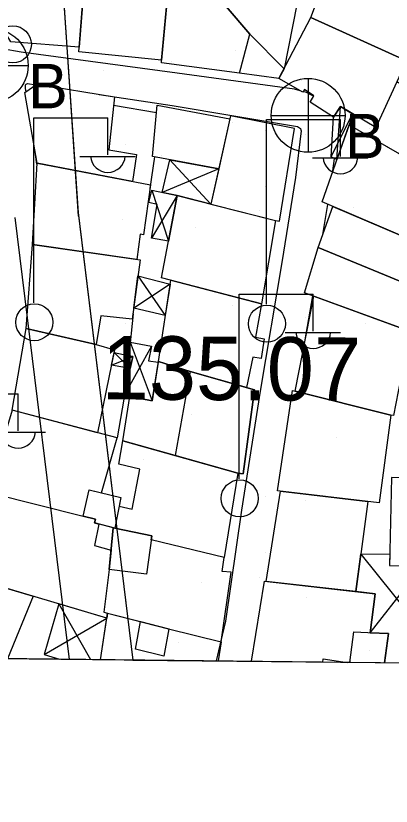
# Model space of a CAD drawing. Extents: x 417997 to 421451, y 4451742 to 4455216.
# Drawn here: x 419917.2 to 419952.7, y 4452223.3 to 4452298.1 of the extents above; entities that cross this region are included whole.
import ezdxf

# ---------------------------------------------------------------- set-up
doc = ezdxf.new("R2010")
doc.units = 0
for name, color, linetype in [('ADAKENARI', 7, 'Continuous'), ('B_Mesken', 7, 'Continuous'), ('B_Sundurma', 7, 'Continuous'), ('B_Teras', 7, 'Continuous'), ('Default', 7, 'Continuous'), ('KALDIRIM', 7, 'Continuous'), ('PAFTALAMA', 7, 'Continuous'), ('PL_AYA_PARK_DINLENME', 7, 'Continuous'), ('S_Elektrik_Diregi', 7, 'Continuous'), ('S_Rogar_Kapagi_Buski', 7, 'Continuous'), ('S_Telefon_Diregi', 7, 'Continuous'), ('Sinir_Duvar_tek_tarafa_ait', 7, 'Continuous'), ('SN_3_DERECE_KAYNAK_KORUMA', 7, 'Continuous'), ('TR_PARKALANI', 7, 'Continuous'), ('Y_Lejant', 7, 'Continuous'), ('Y_Yol_Kotu', 7, 'Continuous'), ('Yol_Sose', 7, 'Continuous')]:
    doc.layers.add(name, color=color, linetype=linetype)

# ---------------------------------------------------------------- blocks, each defined once
blk = doc.blocks.new('POINT_DISPLAY')
at = {"layer": 'Default'}
blk.add_line((0, 0), (0, 0), dxfattribs=at)

msp = doc.modelspace()

# ---------------------------------------------------------------- linework, layer by layer
at = {"layer": 'ADAKENARI'}
for p, q in [((419920.99, 4452309.936), (419923.08, 4452279.148)), ((419920.99, 4452309.936), (419923.08, 4452279.148)), ((419923.023, 4452279.743), (419928.252, 4452237.123)), ((419923.023, 4452279.743), (419928.252, 4452237.123))]:
    msp.add_line(p, q, dxfattribs=at)
at = {"layer": 'B_Mesken'}
for points in [[(419939.424, 4452325.354), (419941.121, 4452325.245), (419941.999, 4452325.172), (419943.003, 4452324.954), (419943.793, 4452324.727), (419944.299, 4452324.44), (419948.562, 4452323.55), (419942.563, 4452293.076), (419939.331, 4452296.35), (419937.073, 4452298.97), (419935.027, 4452300.981), (419932.849, 4452303.798), (419932.01, 4452304.901), (419935.491, 4452308.439), (419936.117, 4452312.075)], [(419923.152, 4452295.121), (419916.688, 4452295.631), (419915.954, 4452296.837), (419915.784, 4452301.664), (419919.479, 4452301.404), (419919.571, 4452303.491), (419923.786, 4452303.169)], [(419927.584, 4452302.656), (419930.972, 4452302.515), (419930.946, 4452302.147), (419931.716, 4452302.062), (419931.533, 4452299.989), (419930.96, 4452293.892), (419923.118, 4452294.684), (419923.786, 4452303.169), (419927.596, 4452302.877)], [(419930.96, 4452293.892), (419931.533, 4452299.989), (419931.716, 4452302.062), (419934.109, 4452301.869), (419933.908, 4452299.403), (419937.073, 4452298.97), (419939.331, 4452296.35), (419942.563, 4452293.076), (419942.08, 4452292.154), (419938.357, 4452292.656), (419930.958, 4452293.656)], [(419946.84, 4452302.53), (419953.318, 4452300.665), (419956.393, 4452299.716), (419954.153, 4452293.827), (419945.105, 4452297.938)], [(419942.08, 4452292.154), (419945.105, 4452297.938), (419954.153, 4452293.827), (419951.245, 4452287.524), (419947.908, 4452289.513), (419947.244, 4452288.513), (419945.034, 4452289.924), (419945.396, 4452290.532), (419944.509, 4452291.116), (419944.337, 4452290.869)], [(419919.168, 4452284.165), (419918.024, 4452290.823), (419919.165, 4452291.642), (419926.506, 4452290.418), (419925.978, 4452285.421), (419928.579, 4452284.98), (419928.221, 4452282.426)], [(419953.241, 4452291.851), (419951.245, 4452287.524), (419950.812, 4452286.575), (419958.642, 4452282.06), (419961.353, 4452287.099)], [(419937.426, 4452288.348), (419936.373, 4452283.625), (419930.094, 4452284.775), (419930.539, 4452289.624)], [(419935.628, 4452280.282), (419941.747, 4452278.73), (419942.132, 4452278.661), (419943.55, 4452287.419), (419937.487, 4452288.624)], [(419946.162, 4452280.478), (419948.729, 4452287.776), (419959.459, 4452281.589), (419958.783, 4452280.37), (419957.717, 4452280.867), (419957.236, 4452279.822), (419956.836, 4452279.967), (419955.263, 4452276.619)], [(419918.744, 4452276.46), (419919.168, 4452284.165), (419929.927, 4452282.098), (419929.239, 4452277.373), (419928.924, 4452277.42), (419928.624, 4452275.037)], [(419930.946, 4452273.292), (419932.455, 4452281.087), (419941.747, 4452278.73), (419940.433, 4452270.846)], [(419945.804, 4452276.164), (419947.174, 4452280.049), (419955.263, 4452276.619), (419963.6, 4452272.95), (419961.522, 4452270.777), (419960.892, 4452270.017), (419955.143, 4452272.331)], [(419918.135, 4452268.488), (419918.744, 4452276.46), (419928.93, 4452274.993), (419928.195, 4452269.391), (419925.227, 4452269.704), (419924.767, 4452267.002)], [(419944.491, 4452271.881), (419945.804, 4452276.164), (419955.143, 4452272.331), (419953.838, 4452268.486)], [(419930.66, 4452265.385), (419931.826, 4452273.065), (419940.433, 4452270.846), (419939.863, 4452267.671), (419940.693, 4452267.535), (419940.396, 4452265.657), (419939.598, 4452265.778), (419939.021, 4452262.921), (419933.657, 4452264.425)], [(419953.838, 4452268.486), (419953.602, 4452267.225), (419954.248, 4452267.072), (419952.919, 4452260.281), (419952.67, 4452260.309), (419943.618, 4452262.575), (419945.396, 4452271.552)], [(419916.828, 4452260.779), (419918.135, 4452268.488), (419924.767, 4452267.002), (419926.521, 4452266.488), (419924.888, 4452258.64)], [(419938.677, 4452254.748), (419938.184, 4452254.822), (419932.242, 4452256.487), (419927.291, 4452257.873), (419927.967, 4452262.069), (419930.071, 4452261.672), (419930.66, 4452265.385), (419933.657, 4452264.425), (419939.764, 4452262.713)], [(419941.931, 4452253.147), (419943.358, 4452262.64), (419952.67, 4452260.309), (419951.565, 4452251.998)], [(419914.871, 4452252.925), (419923.542, 4452250.748), (419924.101, 4452253.219), (419925.263, 4452252.948), (419926.765, 4452258.142), (419916.828, 4452260.779), (419914.467, 4452253.08)], [(419938.184, 4452254.822), (419936.878, 4452246.843), (419929.987, 4452248.501), (419930.04, 4452248.88), (419926.529, 4452249.611), (419926.395, 4452249.639), (419924.613, 4452250.097), (419924.702, 4452250.457), (419923.542, 4452250.748), (419924.101, 4452253.219), (419927.109, 4452252.516), (419926.942, 4452251.681), (419928.192, 4452251.398), (419928.915, 4452255.185), (419926.909, 4452255.678), (419927.291, 4452257.873)], [(419960.577, 4452245.954), (419965.032, 4452245.753), (419965.068, 4452246.939), (419965.168, 4452250.26), (419965.28, 4452254), (419960.71, 4452254.258), (419952.752, 4452254.413), (419952.557, 4452246.079)], [(419925.783, 4452241.103), (419912.794, 4452244.948), (419914.871, 4452252.925), (419923.542, 4452250.748), (419924.702, 4452250.457), (419924.613, 4452250.097), (419925.037, 4452249.988), (419924.602, 4452247.979), (419926.182, 4452247.535), (419925.995, 4452245.694), (419925.488, 4452241.659), (419925.851, 4452241.552)], [(419950.51, 4452252.124), (419949.366, 4452243.608), (419940.885, 4452244.568), (419942.213, 4452253.114)], [(419925.851, 4452241.552), (419925.851, 4452241.552), (419928.954, 4452240.762), (419931.614, 4452240.085), (419936.608, 4452238.845), (419937.55, 4452245.448), (419936.698, 4452245.51), (419936.878, 4452246.843), (419929.987, 4452248.501), (419930.04, 4452248.88), (419926.395, 4452249.639), (419925.995, 4452245.694), (419925.488, 4452241.659)]]:
    msp.add_lwpolyline(points, close=True, dxfattribs=at)
for points in [[(419911.425, 4452237.3), (419909.113, 4452238.595), (419908.815, 4452238.793), (419911.744, 4452245.369), (419912.794, 4452244.948), (419918.801, 4452243.17), (419916.378, 4452237.247)], [(419939.473, 4452237.004), (419940.71, 4452244.588), (419951.177, 4452243.403), (419950.722, 4452239.715), (419952.459, 4452239.624), (419952.082, 4452236.87)], [(419925.188, 4452237.154), (419925.851, 4452241.552), (419931.614, 4452240.085), (419936.608, 4452238.845), (419936.309, 4452237.037)]]:
    msp.add_lwpolyline(points, dxfattribs=at)
at = {"layer": 'B_Sundurma'}
for p, q in [((419947.577, 4452284.5), (419947.908, 4452289.513)), ((419947.029, 4452284.742), (419949.061, 4452288.825)), ((419931.746, 4452284.473), (419935.628, 4452280.282)), ((419936.373, 4452283.625), (419931.036, 4452281.386)), ((419932.455, 4452281.087), (419930.011, 4452277.064)), ((419930.04, 4452281.597), (419931.617, 4452276.758)), ((419928.731, 4452273.475), (419931.319, 4452269.73)), ((419931.772, 4452272.714), (419928.33, 4452270.422)), ((419930.002, 4452266.816), (419927.412, 4452262.176)), ((419927.99, 4452267.195), (419930.071, 4452261.672)), ((419926.465, 4452266.219), (419927.975, 4452264.719)), ((419926.216, 4452265.022), (419928.249, 4452265.841)), ((419949.84, 4452247.139), (419958.103, 4452236.807)), ((419950.722, 4452239.715), (419955.666, 4452246.03)), ((419921.244, 4452242.447), (419924.231, 4452237.165)), ((419919.855, 4452237.665), (419925.783, 4452241.103))]:
    msp.add_line(p, q, dxfattribs=at)
for points in [[(419947.577, 4452284.5), (419947.029, 4452284.742), (419947.244, 4452288.513), (419947.908, 4452289.513), (419949.061, 4452288.825), (419948.729, 4452287.776)], [(419931.746, 4452284.473), (419936.373, 4452283.625), (419935.628, 4452280.282), (419932.455, 4452281.087), (419931.036, 4452281.386)], [(419930.04, 4452281.597), (419932.455, 4452281.087), (419931.617, 4452276.758), (419930.011, 4452277.064), (419930.563, 4452280.24), (419929.745, 4452280.416)], [(419928.731, 4452273.475), (419931.772, 4452272.714), (419931.319, 4452269.73), (419928.33, 4452270.422)], [(419927.99, 4452267.195), (419930.002, 4452266.816), (419929.72, 4452265.447), (419930.647, 4452265.304), (419930.071, 4452261.672), (419927.967, 4452262.069), (419927.412, 4452262.176), (419927.975, 4452264.719), (419928.249, 4452265.841), (419928.249, 4452265.841), (419927.863, 4452265.923)], [(419926.216, 4452265.022), (419926.465, 4452266.219), (419928.249, 4452265.841), (419927.975, 4452264.719)]]:
    msp.add_lwpolyline(points, close=True, dxfattribs=at)
for points in [[(419952.082, 4452236.87), (419952.459, 4452239.624), (419950.722, 4452239.715), (419951.177, 4452243.403), (419949.366, 4452243.608), (419949.84, 4452247.139), (419952.583, 4452247.176), (419952.557, 4452246.079), (419955.666, 4452246.03), (419955.511, 4452241.956), (419958.589, 4452241.941), (419958.147, 4452236.806)], [(419925.188, 4452237.154), (419925.783, 4452241.103), (419921.244, 4452242.447), (419919.855, 4452237.665), (419921.287, 4452237.196)]]:
    msp.add_lwpolyline(points, dxfattribs=at)
at = {"layer": 'B_Teras'}
for points in [[(419923.118, 4452294.684), (419923.786, 4452303.169), (419927.596, 4452302.877), (419927.458, 4452300.416), (419931.533, 4452299.989), (419930.96, 4452293.892)], [(419939.331, 4452296.35), (419942.563, 4452293.076), (419942.08, 4452292.154), (419938.357, 4452292.656)], [(419932.242, 4452256.487), (419938.184, 4452254.822), (419938.677, 4452254.748), (419939.764, 4452262.713), (419933.657, 4452264.425)], [(419923.542, 4452250.748), (419924.101, 4452253.219), (419927.109, 4452252.516), (419926.529, 4452249.611), (419924.613, 4452250.097), (419924.702, 4452250.457)], [(419925.995, 4452245.694), (419926.395, 4452249.639), (419930.04, 4452248.88), (419929.532, 4452245.266)], [(419931.666, 4452240.072), (419931.188, 4452237.505), (419928.501, 4452238.145), (419928.954, 4452240.762)]]:
    msp.add_lwpolyline(points, close=True, dxfattribs=at)
for points in [[(419948.792, 4452236.905), (419949.18, 4452239.795), (419952.459, 4452239.624), (419952.082, 4452236.87)], [(419946.25, 4452236.932), (419946.278, 4452237.232), (419948.551, 4452236.908)]]:
    msp.add_lwpolyline(points, dxfattribs=at)
at = {"layer": 'KALDIRIM'}
msp.add_line((419917.068, 4452279.012), (419922.199, 4452237.187), dxfattribs=at)
msp.add_line((419917.068, 4452279.012), (419922.199, 4452237.187), dxfattribs=at)
at = {"layer": 'PAFTALAMA'}
msp.add_line((419108.72, 4452245.779), (421237.47, 4452223.295), dxfattribs=at)
msp.add_line((419108.72, 4452245.779), (421237.47, 4452223.295), dxfattribs=at)
at = {"layer": 'PL_AYA_PARK_DINLENME'}
for p, q in [((419923.059, 4452279.446), (419928.252, 4452237.123)), ((419923.059, 4452279.446), (419928.252, 4452237.123)), ((419928.252, 4452237.123), (419956.462, 4452236.825)), ((419928.252, 4452237.123), (419956.462, 4452236.825))]:
    msp.add_line(p, q, dxfattribs=at)
msp.add_lwpolyline([(419921.184, 4452321.9), (419920.99, 4452309.936), (419923.059, 4452279.446)], dxfattribs=at)
msp.add_lwpolyline([(419921.184, 4452321.9), (419920.99, 4452309.936), (419923.059, 4452279.446)], dxfattribs=at)
at = {"layer": 'S_Elektrik_Diregi'}
for p, q in [((419918.879, 4452270.927), (419918.879, 4452288.427)), ((419918.879, 4452288.427), (419925.879, 4452288.427)), ((419925.879, 4452284.927), (419925.879, 4452288.427)), ((419940.905, 4452270.795), (419940.904, 4452288.295)), ((419940.904, 4452288.295), (419947.905, 4452288.295)), ((419947.905, 4452284.795), (419947.905, 4452288.295)), ((419923.219, 4452284.787), (419928.469, 4452284.787)), ((419945.245, 4452284.655), (419950.495, 4452284.655)), ((419938.325, 4452254.262), (419938.325, 4452271.762)), ((419938.325, 4452271.762), (419945.325, 4452271.762)), ((419945.325, 4452268.262), (419945.325, 4452271.762)), ((419942.665, 4452268.122), (419947.915, 4452268.122)), ((419910.369, 4452262.319), (419917.369, 4452262.319)), ((419917.369, 4452258.819), (419917.369, 4452262.319)), ((419914.709, 4452258.679), (419919.959, 4452258.679))]:
    msp.add_line(p, q, dxfattribs=at)
for centre in [(419918.915, 4452269.092), (419940.94, 4452268.96), (419938.361, 4452252.427)]:
    msp.add_circle(centre, 1.75, dxfattribs=at)
for centre in [(419925.879, 4452284.94), (419947.905, 4452284.808), (419945.325, 4452268.275), (419917.37, 4452258.832)]:
    msp.add_arc(centre, 1.658, 184.83843, 355.14641, dxfattribs=at)
at = {"layer": 'S_Rogar_Kapagi_Buski'}
for p, q in [((419911.332, 4452293.406), (419918.332, 4452293.406)), ((419944.841, 4452292.176), (419944.841, 4452285.176)), ((419941.341, 4452288.676), (419948.341, 4452288.676))]:
    msp.add_line(p, q, dxfattribs=at)
for centre in [(419914.832, 4452293.406), (419944.841, 4452288.676)]:
    msp.add_circle(centre, 3.5, dxfattribs=at)
at = {"layer": 'S_Telefon_Diregi'}
msp.add_circle((419916.879, 4452295.392), 1.754, dxfattribs=at)
at = {"layer": 'Sinir_Duvar_tek_tarafa_ait'}
for points in [[(419926.423, 4452289.634), (419930.477, 4452288.955)], [(419929.875, 4452281.742), (419930.311, 4452284.736)], [(419928.259, 4452269.879), (419927.863, 4452265.923)], [(419927.886, 4452264.734), (419926.765, 4452258.142)]]:
    msp.add_lwpolyline(points, dxfattribs=at)
at = {"layer": 'SN_3_DERECE_KAYNAK_KORUMA'}
msp.add_line((419108.72, 4452245.779), (420357.813, 4452232.586), dxfattribs=at)
msp.add_line((419108.72, 4452245.779), (420357.813, 4452232.586), dxfattribs=at)
at = {"layer": 'Y_Lejant'}
msp.add_lwpolyline([(419138.442, 4455021.89), (421266.409, 4454999.402), (421237.471, 4452223.294), (419108.722, 4452245.778)], close=True, dxfattribs=at)
at = {"layer": 'Yol_Sose'}
for points in [[(419944.103, 4452291.002), (419943.568, 4452291.153), (419932.436, 4452292.669), (419917.667, 4452294.654), (419915.868, 4452294.965), (419915.754, 4452294.992), (419915.609, 4452295.119), (419915.51, 4452295.29), (419915.499, 4452295.349), (419914.299, 4452304.561)], [(419918.128, 4452290.898), (419918.102, 4452291.061), (419918.079, 4452291.217), (419918.067, 4452291.382), (419918.075, 4452291.498), (419918.082, 4452291.526), (419918.094, 4452291.55), (419918.148, 4452291.628), (419918.259, 4452291.697), (419919.07, 4452291.574)], [(419925.058, 4452290.659), (419931.954, 4452289.607)], [(419945.37, 4452290.489), (419945.236, 4452290.568), (419944.699, 4452290.834), (419944.376, 4452290.925)], [(419931.954, 4452289.607), (419943.851, 4452287.623), (419943.943, 4452287.568), (419944.107, 4452287.421), (419944.162, 4452287.301), (419944.198, 4452287.206), (419943.654, 4452282.805), (419942.359, 4452274.754), (419940.303, 4452262.583), (419938.53, 4452251.321), (419937.014, 4452240.809), (419936.698, 4452239.475)], [(419919.162, 4452284.051), (419918.991, 4452285.196)], [(419947.195, 4452283.414), (419947.346, 4452284.602)], [(419946.235, 4452277.387), (419946.7, 4452280.25)], [(419944.397, 4452266.508), (419945.274, 4452271.596)], [(419936.698, 4452239.475), (419936.12, 4452237.039)]]:
    msp.add_lwpolyline(points, dxfattribs=at)

# ---------------------------------------------------------------- block references
at = {"layer": 'TR_PARKALANI', "xscale": 0.1, "yscale": 0.10000000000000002}
for p in [(419938.008, 4452294.804), (419938.008, 4452294.804), (419931.884, 4452293.799), (419931.884, 4452293.799), (419925.487, 4452292.885), (419925.487, 4452292.885), (419944.236, 4452291.959), (419944.236, 4452291.959), (419937.645, 4452288.014), (419937.645, 4452288.014), (419940.799, 4452287.227), (419940.799, 4452287.227), (419944.551, 4452286.889), (419944.551, 4452286.889), (419950.619, 4452287.402), (419950.619, 4452287.402), (419927.589, 4452285.939), (419927.589, 4452285.939), (419930.971, 4452284.843), (419930.971, 4452284.843), (419940.799, 4452281.962), (419940.799, 4452281.962), (419940.271, 4452279.624), (419940.271, 4452279.624), (419949.157, 4452279.908), (419949.157, 4452279.908), (419927.224, 4452278.811), (419927.224, 4452278.811), (419934.169, 4452278.08), (419934.169, 4452278.08), (419937.645, 4452270.715), (419937.645, 4452270.715), (419927.589, 4452268.941), (419927.589, 4452268.941), (419944.551, 4452269.59), (419944.551, 4452269.59), (419950.254, 4452268.941), (419950.254, 4452268.941), (419940.271, 4452262.325), (419940.271, 4452262.325), (419933.804, 4452260.35), (419933.804, 4452260.35), (419947.512, 4452258.157), (419947.512, 4452258.157), (419929.234, 4452256.146), (419929.234, 4452256.146), (419937.645, 4452253.371), (419937.645, 4452253.371), (419940.799, 4452252.584), (419940.799, 4452252.584), (419944.551, 4452252.247), (419944.551, 4452252.247), (419940.799, 4452247.319), (419940.799, 4452247.319), (419940.271, 4452244.982), (419940.271, 4452244.982), (419934.718, 4452244.448), (419934.718, 4452244.448), (419944.663, 4452243.091), (419944.663, 4452243.091), (419932.524, 4452238.782), (419932.524, 4452238.782), (419950.619, 4452238.051), (419950.619, 4452238.051)]:
    msp.add_blockref('POINT_DISPLAY', p, dxfattribs=at)

# ---------------------------------------------------------------- texts
at = {"layer": 'S_Rogar_Kapagi_Buski'}
for p in [(419918.332, 4452289.342), (419948.341, 4452284.612)]:
    msp.add_text('B', height=4.2, dxfattribs=at).set_placement(p)
at = {"layer": 'Y_Yol_Kotu'}
msp.add_text('135.07 ', height=6, rotation=359.61735, dxfattribs=at).set_placement((419925.291, 4452261.805))

doc.saveas('drawing.dxf')
